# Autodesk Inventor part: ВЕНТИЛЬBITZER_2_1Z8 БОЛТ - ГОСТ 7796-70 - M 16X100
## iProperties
Created: 2011-02
Part Number: ВЕНТИЛЬBITZER_2_1Z8 БОЛТ - ГОСТ 7796-70 - M 16X100
Document SubType Name: Modeling
Designer: Чернышев Юрий
Mass: 23.746 g
Surface Area: 65.2372 cm^2
Volume: 23.746 cm^3
Density: 1 g/cm^3
Author: Чернышев Юрий
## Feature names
1. Base1
